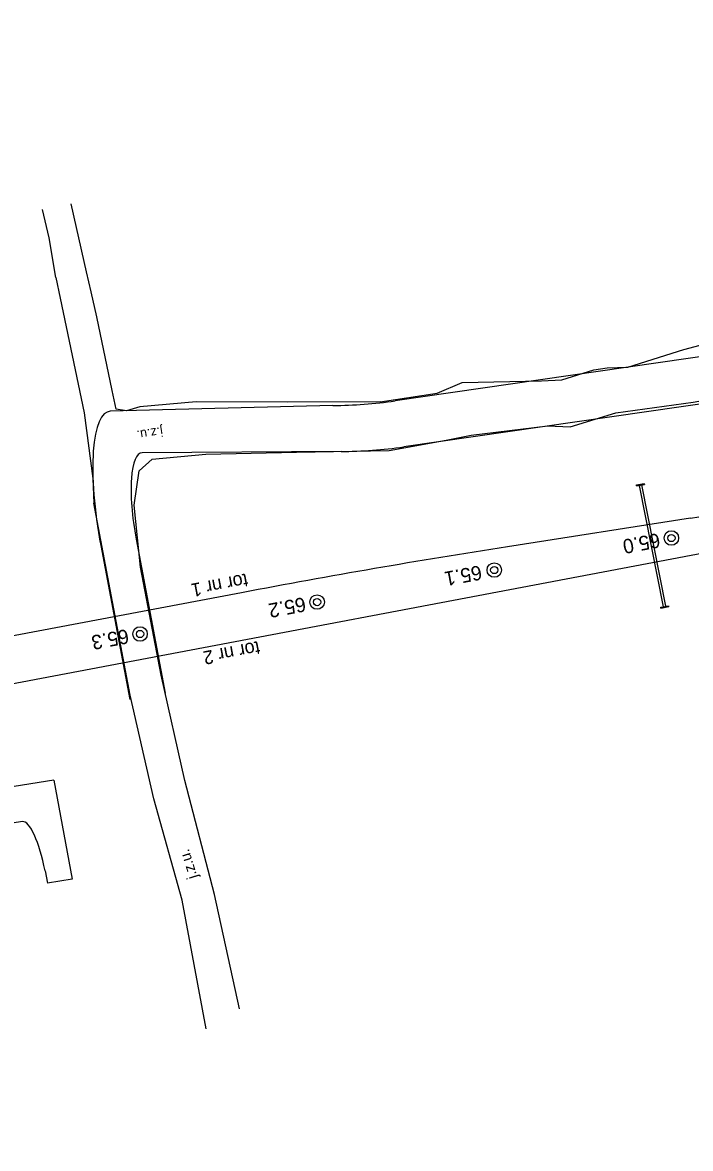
# Model space of a CAD drawing. Extents: x 6541740 to 6556805, y 5525233 to 5530361.
# Drawn here: x 6556251.3 to 6556344.1, y 5525917.2 to 5526073.7 of the extents above; entities that cross this region are included whole.
import ezdxf

# ---------------------------------------------------------------- set-up
doc = ezdxf.new("R2010")
doc.units = 0
for name, color, linetype in [('Default', 7, 'Continuous'), ('TOR_PS_OPIS_T-numeracja torow i rozjazdow', 7, 'Continuous'), ('TOR_SCH-hektometry', 7, 'Continuous'), ('TOR_SCH-obiekty istniejace', 7, 'Continuous'), ('TOR_SCH-przejazdy+drogi istniejace', 7, 'Continuous'), ('TOR_SCH-przejazdy+drogi projektowane', 7, 'Continuous'), ('TOR_SCH-tory projektowane', 7, 'Continuous')]:
    doc.layers.add(name, color=color, linetype=linetype)

# ---------------------------------------------------------------- blocks, each defined once
blk = doc.blocks.new('4010_1')
at = {"layer": 'Default'}
for radius in [0.75, 0.375]:
    blk.add_circle((0, 0), radius, dxfattribs=at)

msp = doc.modelspace()

# ---------------------------------------------------------------- linework, layer by layer
at = {"layer": 'TOR_SCH-obiekty istniejace'}
for p, q in [((6556336.64, 5526009.46), (6556337.72, 5526009.67)), ((6556337.72, 5526009.67), (6556337.74, 5526009.54)), ((6556336.66, 5526009.34), (6556336.64, 5526009.46)), ((6556336.66, 5526009.34), (6556337.74, 5526009.54)), ((6556337, 5526009.4), (6556340.35, 5525992.53)), ((6556340.72, 5525992.6), (6556337.4, 5526009.48)), ((6556340.02, 5525992.47), (6556341.1, 5525992.67)), ((6556340.04, 5525992.35), (6556340.02, 5525992.47)), ((6556340.04, 5525992.35), (6556341.12, 5525992.55)), ((6556341.1, 5525992.67), (6556341.12, 5525992.55))]:
    msp.add_line(p, q, dxfattribs=at)
at = {"layer": 'TOR_SCH-przejazdy+drogi istniejace'}
for points in [[(6556255.95, 5526038.27), (6556255.03, 5526043.81), (6556254.1, 5526047.73)], [(6556260.23, 5526039.09), (6556258.82, 5526045.24), (6556258.07, 5526048.51)], [(6556255.95, 5526038.27), (6556256.55, 5526035.4)], [(6556260.87, 5526036.28), (6556260.23, 5526039.09)], [(6556301.03, 5526021), (6556288.21, 5526020.95), (6556275.48, 5526020.99), (6556267.64, 5526020.32), (6556265.78, 5526019.75), (6556264.35, 5526020.01), (6556263.81, 5526022.57), (6556261.66, 5526032.81), (6556260.87, 5526036.28)], [(6556256.55, 5526035.4), (6556259.91, 5526019.5), (6556261.1, 5526010.35), (6556261.22, 5526006.94)], [(6556301.03, 5526021), (6556308.94, 5526022.23), (6556312.43, 5526023.7), (6556323.46, 5526023.91), (6556326.25, 5526024.08), (6556330.73, 5526025.47), (6556332.55, 5526025.73), (6556335.44, 5526025.81), (6556343.2, 5526028.3), (6556350.37, 5526030.18), (6556357.54, 5526030.26)], [(6556302.27, 5526014.25), (6556310.2, 5526015.68), (6556313.66, 5526016.39), (6556324.34, 5526017.68), (6556327.42, 5526017.52), (6556333.76, 5526019.49), (6556344.51, 5526020.95), (6556348.22, 5526021.61), (6556351.75, 5526022.37), (6556358.96, 5526022.02)], [(6556267.54, 5526011.43), (6556269.35, 5526013.06), (6556276.8, 5526013.75), (6556289.42, 5526014.01), (6556302.27, 5526014.25)], [(6556281.47, 5525936.63), (6556278.01, 5525952.52), (6556273.89, 5525968.39), (6556270.61, 5525983.01), (6556267.74, 5525998.02), (6556266.85, 5526006.66), (6556267.54, 5526011.43)], [(6556276.87, 5525933.88), (6556273.5, 5525951.75), (6556269.56, 5525965.85), (6556266.29, 5525980.26), (6556261.22, 5526006.94)]]:
    msp.add_lwpolyline(points, dxfattribs=at)
at = {"layer": 'TOR_SCH-przejazdy+drogi projektowane'}
for p, q in [((6556371.87, 5526031.08), (6556303.1, 5526021.15)), ((6556374.8, 5526024.94), (6556304.29, 5526014.76)), ((6556294.46, 5526020.5), (6556263.53, 5526019.69)), ((6556295.59, 5526014.11), (6556267.97, 5526013.92)), ((6556267.12, 5526001.9), (6556271.13, 5525980.52)), ((6556262.21, 5526001.03), (6556266.22, 5525979.65)), ((6556255.66, 5525968.41), (6556228.1, 5525964.02)), ((6556255.66, 5525968.41), (6556258.24, 5525954.65)), ((6556254.46, 5525955.82), (6556254.78, 5525954.1)), ((6556258.24, 5525954.65), (6556254.78, 5525954.1))]:
    msp.add_line(p, q, dxfattribs=at)
msp.add_lwpolyline([(6556251.33, 5525962.66), (6556229.03, 5525959.1), (6556228.42, 5525958.25)], dxfattribs=at)
for centre, major_axis, start_param, end_param in [((6556120.17, 5527000.91), (-185.63, 979.31), 3.096033, 3.1306), ((6556266.72, 5526001.74), (-3.4, 17.93), 6.237625, 7.846281), ((6556120.17, 5527000.91), (-186.84, 985.7), 3.096033, 3.1306), ((6556270.03, 5526002.36), (-2.19, 11.54), 6.237625, 7.846281), ((6556252.67, 5525955.54), (-1.35, 7.12), 4.705111, 6.275907)]:
    msp.add_ellipse(centre, major_axis=major_axis, ratio=0.25, start_param=start_param, end_param=end_param, dxfattribs=at)
at = {"layer": 'TOR_SCH-tory projektowane'}
for p, q in [((6556735.03, 5526073.73), (6555909.41, 5525917.23)), ((6556344.14, 5526004.83), (6556318.73, 5526000.87)), ((6556281.77, 5525994.48), (6556246.88, 5525987.87))]:
    msp.add_line(p, q, dxfattribs=at)
for centre, start_param, end_param in [((6552935.72, 5544187.56), 3.133485, 3.141593), ((6559727.15, 5507818.14), 6.275077, 6.283185)]:
    msp.add_ellipse(centre, major_axis=(-3445.38, 18176.34), ratio=0.25, start_param=start_param, end_param=end_param, dxfattribs=at)

# ---------------------------------------------------------------- block references
at = {"layer": 'TOR_SCH-hektometry', "xscale": 1.345963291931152, "yscale": 1.345963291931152}
for p in [(6556341.49, 5526002.08), (6556316.88, 5525997.63), (6556292.26, 5525993.18), (6556267.66, 5525988.74)]:
    msp.add_blockref('4010_1', p, dxfattribs=at)

# ---------------------------------------------------------------- texts
at = {"layer": 'TOR_PS_OPIS_T-numeracja torow i rozjazdow'}
for s, p in [('tor nr 1', (6556282.45, 5525997.17)), ('tor nr 2', (6556284.12, 5525987.77))]:
    msp.add_text(s, height=1.875, rotation=190.7101, dxfattribs=at).set_placement(p)
at = {"layer": 'TOR_SCH-hektometry'}
for s, p in [('65.0', (6556339.71, 5526002.79)), ('65.1', (6556314.94, 5525998.31)), ('65.2', (6556290.48, 5525993.89)), ('65.3', (6556265.89, 5525989.45))]:
    msp.add_text(s, height=2, rotation=190.7691, dxfattribs=at).set_placement(p)
at = {"layer": 'TOR_SCH-przejazdy+drogi istniejace'}
for height, rotation, p in [(1.293, 188.9064, (6556270.74, 5526017.54)), (1.497, 107.2313, (6556275.67, 5525954.94))]:
    msp.add_text('j.z.u.', height=height, rotation=rotation, dxfattribs=at).set_placement(p)

doc.saveas('drawing.dxf')
